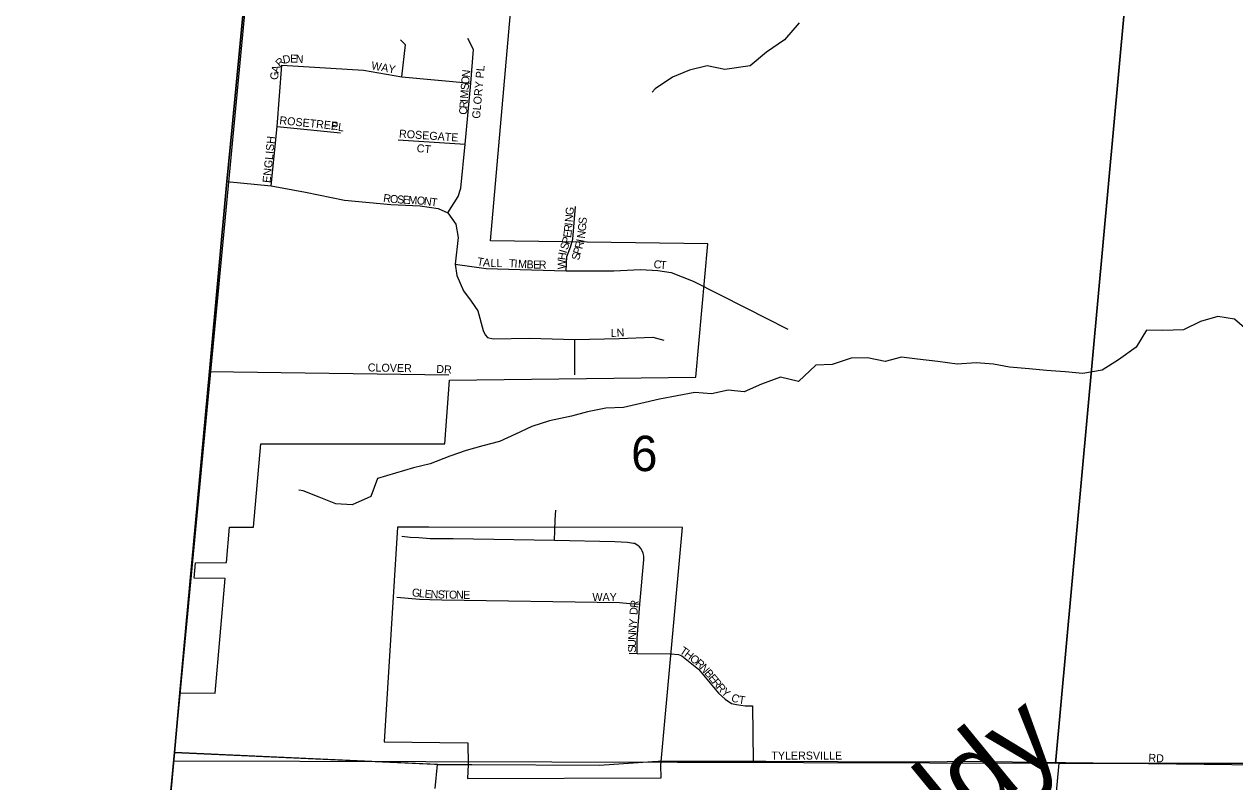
# Model space of a CAD drawing. Extents: x 1310247 to 1664935, y 284496 to 704931.
# Drawn here: x 1445055 to 1452617, y 497520 to 502251 of the extents above; entities that cross this region are included whole.
import ezdxf

# ---------------------------------------------------------------- set-up
doc = ezdxf.new("R2010")
doc.units = 0
for name, color, linetype in [('GM_P_State_Location', 7, 'Continuous'), ('GM_X_Adjacent_County_Text', 7, 'Continuous'), ('GM_X_Corporation_Text', 7, 'Continuous'), ('GM_X_County', 7, 'Continuous'), ('GM_X_County_Road_Text', 7, 'Continuous'), ('GM_X_Major_Lake_Text', 7, 'Continuous'), ('GM_X_Minor_Lake_Text', 7, 'Continuous'), ('GM_X_Minor_River_Text', 7, 'Continuous'), ('GM_X_Rail_Line', 7, 'Continuous'), ('GM_X_State_Location', 7, 'Continuous'), ('GM_X_Township', 7, 'Continuous'), ('GM_X_US_Location', 7, 'Continuous')]:
    doc.layers.add(name, color=color, linetype=linetype)

msp = doc.modelspace()

# ---------------------------------------------------------------- linework, layer by layer
at = {"layer": 'GM_X_Adjacent_County_Text'}
msp.add_lwpolyline([(1446894.5, 506785.7), (1446717.8, 505262.3), (1446712.9, 505216.6), (1446629.5, 504462.9), (1446548.8, 503678.3), (1446491.2, 503041.2), (1446353.3, 501607.9), (1446320.8, 501270), (1446211.6, 500082.3), (1446026.9, 498075.2), (1445993, 497703.6), (1445785.8, 495446.6), (1445732.6, 494862.7), (1445681.3, 494266.4), (1445592.7, 493387.5), (1445549.2, 492941.9), (1445497, 492347.4), (1445389.8, 491098.1), (1445360.5, 490723.4), (1445054.9, 487578.1)], dxfattribs=at)
at = {"layer": 'GM_X_Corporation_Text'}
for points in [[(1449095.1, 498320.1), (1449142.2, 498314.4), (1449163.5, 498305.9), (1449267.4, 498223.3), (1449391.3, 498073.8), (1449432.6, 498035.4), (1449472.5, 498008.3), (1449505.2, 498002.6), (1449559.3, 497994.1), (1449603.4, 497994.1), (1449609.1, 497648.5)], [(1447617.1, 497629.6), (1447637.4, 497628.6), (1447826.8, 497627.6)], [(1448979.8, 497646.1), (1449014.6, 497648.5), (1449609.1, 497648.5), (1449688.6, 497648.5), (1450586.2, 497645.6), (1450821.2, 497647.8)], [(1450821.2, 497647.8), (1450897.9, 497648.5), (1451559.9, 497639.6), (1452770.9, 497625.1)]]:
    msp.add_lwpolyline(points, dxfattribs=at)
at = {"layer": 'GM_X_County'}
for points in [[(1446558.4, 503634.8), (1451866.7, 503067.5), (1451992.5, 503054.9), (1451497.4, 497635.4), (1445990.1, 497648.6)], [(1451992.5, 503054.9), (1457222.9, 502513.6), (1456790.6, 497630.8), (1451519.4, 497637), (1451497.4, 497635.4)], [(1456790.6, 497630.8), (1456780, 497501.1), (1456291.7, 492217.5), (1451025.9, 492295.4), (1451519.4, 497637)]]:
    msp.add_lwpolyline(points, close=True, dxfattribs=at)
at = {"layer": 'GM_X_County_Road_Text'}
for points in [[(1446026.1, 498065.6), (1446026.9, 498075.2), (1446211.6, 500082.3), (1446320.8, 501270), (1446353.3, 501607.9), (1446489.9, 503027)], [(1445993, 497703.6), (1446026.1, 498065.6)], [(1445959, 497333.5), (1445993, 497703.6)], [(1445993, 497703.6), (1447617.1, 497629.6)], [(1447826.8, 497627.6), (1447850.2, 497627.5), (1448648, 497623.3), (1448979.8, 497646.1)]]:
    msp.add_lwpolyline(points, dxfattribs=at)
at = {"layer": 'GM_X_Major_Lake_Text'}
msp.add_lwpolyline([(1447621, 497477.3), (1447637.4, 497628.6), (1445993, 497703.6), (1446026.9, 498075.2), (1446247.5, 498073.5), (1446310.3, 498790), (1446116.4, 498791.3), (1446124.5, 498888.4), (1446319, 498889.6), (1446338.3, 499109.6), (1446488.2, 499109.6), (1446533.9, 499631.3), (1447682.9, 499631.3), (1447711.7, 500028.4), (1449250.6, 500047.4), (1449325.5, 500879), (1447967.9, 500899.4), (1448113.5, 502561.9)], dxfattribs=at)
msp.add_lwpolyline([(1447583.3, 499111.1), (1447387.7, 499111.1), (1447303.6, 497768.8), (1447825.9, 497764.3), (1447828.2, 497627.6), (1447824.7, 497540), (1449032.8, 497544.2), (1449032.4, 497623), (1449166.1, 499108.1)], close=True, dxfattribs=at)
at = {"layer": 'GM_X_Minor_River_Text'}
for points in [[(1449895.6, 502260.1), (1449803.2, 502153.8), (1449690.9, 502077.7), (1449590.6, 501991.5), (1449432, 501969.4), (1449321.7, 501991.5), (1449211.3, 501965.4), (1449105, 501921.3), (1448996.7, 501847.2), (1448978.6, 501827.1)], [(1452726.4, 500313.8), (1452616, 500410), (1452511.7, 500426), (1452403.4, 500394), (1452297, 500341.9), (1452166.6, 500337.8), (1452066.3, 500339.8), (1452000.1, 500233.6), (1451889.7, 500155.4), (1451789.4, 500091.3), (1451667, 500069.2), (1451556.7, 500081.3), (1451440.3, 500089.3), (1451332, 500099.3), (1451209.6, 500109.3), (1451109.3, 500129.4), (1451000.9, 500137.4), (1450882.5, 500127.4), (1450762.2, 500145.4), (1450635.7, 500159.4), (1450535.4, 500171.5), (1450433.1, 500145.4), (1450322.8, 500167.5), (1450220.4, 500165.5), (1450102, 500125.4), (1449999.7, 500121.3), (1449891.4, 500019.1), (1449779, 500047.2), (1449660.6, 500003.1), (1449552.3, 499955), (1449452, 499967), (1449347.6, 499943), (1449243.3, 499951), (1449132.9, 499930.9), (1449022.6, 499908.9), (1448906.2, 499882.8), (1448797.9, 499856.8), (1448687.5, 499852.8), (1448573.1, 499830.7), (1448472.8, 499804.6), (1448336.4, 499774.6), (1448226, 499738.5), (1448123.7, 499690.4), (1448023.4, 499646.3), (1447919, 499618.2), (1447814.7, 499588.2), (1447714.4, 499554.1), (1447590, 499506), (1447487.7, 499481.9), (1447260.9, 499413.8), (1447220.8, 499301.5), (1447104.4, 499249.4), (1447002.1, 499255.4), (1446897.8, 499297.5), (1446797.4, 499337.6), (1446771.4, 499341.6)]]:
    msp.add_lwpolyline(points, dxfattribs=at)
at = {"layer": 'GM_X_State_Location'}
for points in [[(1447414.8, 501923.4), (1447437.6, 502123), (1447406.4, 502154.3)], [(1447701.7, 501073), (1447764.9, 501174.7), (1447781.8, 501228.6), (1447810.3, 501503.3), (1447845.2, 501882.3), (1447862.3, 502093.7), (1447826.2, 502162.1)], [(1446597, 501242.9), (1446635.8, 501612.2), (1446664.3, 501995.2), (1447174.5, 501964.4), (1447414.8, 501923.4), (1447845.2, 501882.3)], [(1446635.8, 501612.2), (1447031.7, 501573.6)], [(1447391.7, 501530.4), (1447810.3, 501503.3)], [(1446320.8, 501270), (1446597, 501242.9), (1446811.4, 501202.4), (1447054.8, 501153.1), (1447344.3, 501125.4), (1447529.2, 501116.2), (1447640.1, 501100.8), (1447701.7, 501073), (1447751, 501002.2), (1447766.4, 500919), (1447747.9, 500752.6), (1447757.1, 500681.8), (1447799.3, 500587.3), (1447847.2, 500521.8), (1447888.2, 500461.3), (1447922.4, 500338.3), (1447934.6, 500310.9), (1447949.7, 500294.3), (1447984.9, 500285.6), (1448211, 500291.6), (1448494.2, 500282.3), (1448771.9, 500289), (1448981.2, 500297.9), (1449051, 500278.7)], [(1448439.6, 500711.4), (1448444.2, 500800.4), (1448467.2, 500858.9), (1448481.1, 500909.8), (1448498.1, 501113.1)], [(1447747.9, 500752.6), (1447940.4, 500726.5), (1448223.9, 500717.2), (1448439.6, 500711.4), (1448738.3, 500711), (1448904.7, 500720.3), (1449012.5, 500714.1), (1449095.7, 500701.8), (1449234.3, 500646.3), (1449557.8, 500483.1), (1449825.8, 500347.5)], [(1448493.5, 500061.8), (1448494.2, 500282.3)], [(1446211.6, 500082.3), (1447707.9, 500062.6)], [(1448368.2, 499026.5), (1448368.8, 499089.9), (1448371.2, 499153.2), (1448375.5, 499216.4)], [(1448883.7, 498321.8), (1448884.8, 498414.1), (1448900, 498630.1), (1448925.7, 498906.2), (1448925.7, 498927.7), (1448923.7, 498939.1), (1448921.4, 498948.9), (1448915.5, 498962.7), (1448908.3, 498975.3), (1448897.8, 498986.6), (1448888.8, 498995.3), (1448877.8, 499002.7), (1448869.2, 499007.4), (1448861, 499009.1), (1448822.5, 499014), (1448783.9, 499017.1), (1448745.2, 499018.5), (1448368.2, 499026.5), (1447734.8, 499036.8), (1447663, 499036.5), (1447591.2, 499038.5), (1447519.5, 499042.8), (1447466.2, 499046.6), (1447412.9, 499051.1)], [(1447383.4, 498673.7), (1447525, 498661.5), (1447588.5, 498658.1), (1447662.9, 498655.5), (1448774.4, 498640), (1448837.1, 498634.1), (1448900, 498630.1)], [(1448834.4, 498323.9), (1448883.7, 498321.8), (1449095.1, 498320.1)]]:
    msp.add_lwpolyline(points, dxfattribs=at)
at = {"layer": 'GM_X_Township'}
msp.add_lwpolyline([(1445054.9, 487578.1), (1445360.5, 490723.4), (1445389.8, 491098.1), (1445497, 492347.4), (1445549.2, 492941.9), (1445592.7, 493387.5), (1445681.3, 494266.4), (1445732.6, 494862.7), (1445785.8, 495446.6), (1445993, 497703.6), (1446026.9, 498075.2), (1446211.6, 500082.3), (1446320.8, 501270), (1446353.3, 501607.9), (1446491.2, 503041.2), (1446548.8, 503678.3), (1446629.5, 504462.9), (1446712.9, 505216.6), (1446717.8, 505262.3), (1446894.5, 506785.7)], dxfattribs=at)

# ---------------------------------------------------------------- texts
at = {"layer": 'GM_P_State_Location'}
for s, rotation, p in [('D', 12.36102, (1446675.2, 502003.7)), ('E', 357.27517, (1446714.7, 502012.8)), ('N', 357.27517, (1446749.9, 502011.2)), ('A', 72.70444, (1446642.7, 501943.9)), ('R', 42.53273, (1446652.1, 501980.1)), ('WAY', 349.69341, (1447220, 501970.6)), ('GLORY PL', 84.96036, (1447901.8, 501659.8)), ('G', 87.79029, (1446641.6, 501903.4)), ('O', 84.41771, (1447833.2, 501873.2)), ('N', 83.69359, (1447837.5, 501916.8)), ('M', 86.17444, (1447827.3, 501785.8)), ('S', 85.98055, (1447830.8, 501838.4)), ('R', 86.18825, (1447823.2, 501724.3)), ('I', 86.15103, (1447825.8, 501763.8)), ('ROSETREE', 354.28941, (1446647.2, 501627.5)), ('C', 86.16007, (1447820.5, 501684.8)), ('PL', 352.39486, (1446968.7, 501592.3)), ('ENGLISH', 84.19295, (1446592.9, 501258.3)), ('ROSEGATE', 356.08102, (1447394.9, 501544)), ('CT', 353.66381, (1447504.6, 501454)), ('R', 351.05262, (1447294.7, 501143.4)), ('O', 355.25138, (1447337.8, 501136.8)), ('S', 357.17567, (1447383.5, 501133)), ('E', 357.21452, (1447418.7, 501131.3)), ('M', 357.23039, (1447453.9, 501129.6)), ('O', 355.27447, (1447506.1, 501127.1)), ('N', 352.70147, (1447549.4, 501123.5)), ('T', 352.57684, (1447593, 501117.9)), ('G', 84.80048, (1448485, 501057.3)), ('R', 84.73285, (1448475.4, 500952.1)), ('I', 84.80647, (1448479.1, 500991.6)), ('N', 84.79171, (1448481.1, 501013.5)), ('G', 84.37211, (1448562.2, 500956.3)), ('S', 84.62981, (1448566.5, 501000.3)), ('P', 74.13322, (1448459.4, 500873.4)), ('E', 82.51369, (1448470.6, 500915.1)), ('N', 82.62101, (1448556.3, 500911)), ('I', 73.05794, (1448442.1, 500817.5)), ('S', 72.62804, (1448448.4, 500838.5)), ('P', 72.48951, (1448529.1, 500808.2)), ('R', 74.47422, (1448540.2, 500843.6)), ('I', 79.663, (1448551.9, 500886.6)), ('T', 349.92637, (1447880.9, 500747.2)), ('A', 353.95582, (1447919.4, 500740.5)), ('L', 357.98527, (1447967, 500735.6)), ('L', 0.00001, (1448004.1, 500734.3)), ('T', 356.55491, (1448081.3, 500734.4)), ('I', 356.54367, (1448116.4, 500732.2)), ('M', 356.56663, (1448138.4, 500730.9)), ('B', 357.40878, (1448191.9, 500727.7)), ('E', 359.54886, (1448233.4, 500725.8)), ('R', 359.96866, (1448269, 500725.6)), ('W', 89.66375, (1448436.5, 500720.5)), ('H', 82.39235, (1448436.7, 500776)), ('S', 78.13808, (1448522.2, 500775)), ('C', 352.86595, (1448984.2, 500729.9)), ('T', 354.47756, (1449025.1, 500724.8)), ('L', 0.81963, (1448718.9, 500298.8)), ('N', 4.24846, (1448757.3, 500299.4)), ('CLOVER', 358.97753, (1447200.8, 500083.2)), ('DR', 356.82219, (1447628, 500074.3)), ('G', 353.49571, (1447474.6, 498679.5)), ('L', 353.5103, (1447518.3, 498674.5)), ('E', 354.55588, (1447554.3, 498670.4)), ('N', 358.29262, (1447592.9, 498666.9)), ('S', 359.05283, (1447637.6, 498665.6)), ('T', 359.04379, (1447672.8, 498665)), ('O', 359.04692, (1447708, 498664.4)), ('N', 359.06943, (1447752, 498663.6)), ('E', 359.04379, (1447796, 498662.9)), ('WAY', 0.00001, (1448604.3, 498648.8)), ('R', 82.37485, (1448888.4, 498603.7)), ('D', 85.82092, (1448885.3, 498560.6)), ('Y', 86.06233, (1448881.8, 498493.1)), ('N', 87.24457, (1448876.7, 498405.5)), ('N', 86.08413, (1448878.8, 498449.2)), ('S', 89.94534, (1448876.5, 498327)), ('U', 89.67209, (1448876.5, 498362.1))]:
    msp.add_text(s, height=50, rotation=rotation, dxfattribs=at).set_placement(p)
at = {"layer": 'GM_X_Minor_Lake_Text'}
msp.add_text('Muddy', height=500, rotation=39.32332, dxfattribs=at).set_placement((1450001.6, 496445.7))
at = {"layer": 'GM_X_Rail_Line'}
for s, rotation, p in [('T', 326.47667, (1449145.4, 498326.6)), ('H', 322.25153, (1449174, 498307.7)), ('O', 321.4426, (1449208.6, 498280.9)), ('R', 319.8991, (1449242.8, 498253.7)), ('N', 311.96935, (1449271.7, 498229.4)), ('B', 309.75583, (1449300.8, 498197.1)), ('E', 309.71812, (1449326.2, 498166.7)), ('R', 309.70176, (1449348.6, 498139.6)), ('R', 310.53048, (1449374.5, 498108.5)), ('Y', 318.66832, (1449405.6, 498072.9)), ('C', 339.62177, (1449466.6, 498026.3)), ('T', 351.11397, (1449514.3, 498009.7)), ('TYLERSVILLE', 0.00001, (1449721.9, 497658.8)), ('RD', 356.97695, (1452076.4, 497645.6))]:
    msp.add_text(s, height=50, rotation=rotation, dxfattribs=at).set_placement(p)
at = {"layer": 'GM_X_US_Location'}
msp.add_text('6', height=221, rotation=0.00001, dxfattribs=at).set_placement((1448846.3, 499460.3))

doc.saveas('drawing.dxf')
